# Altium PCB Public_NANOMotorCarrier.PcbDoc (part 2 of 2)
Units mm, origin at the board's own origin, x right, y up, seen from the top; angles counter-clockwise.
Board outline 50 x 80 mm, 4 copper layers (Top, PWR, GND, Bottom), stack 1.612 mm thick; 200 components, 139 nets, 723 pads, 320 vias.
Unrouted connection lines stored in the file: 53.
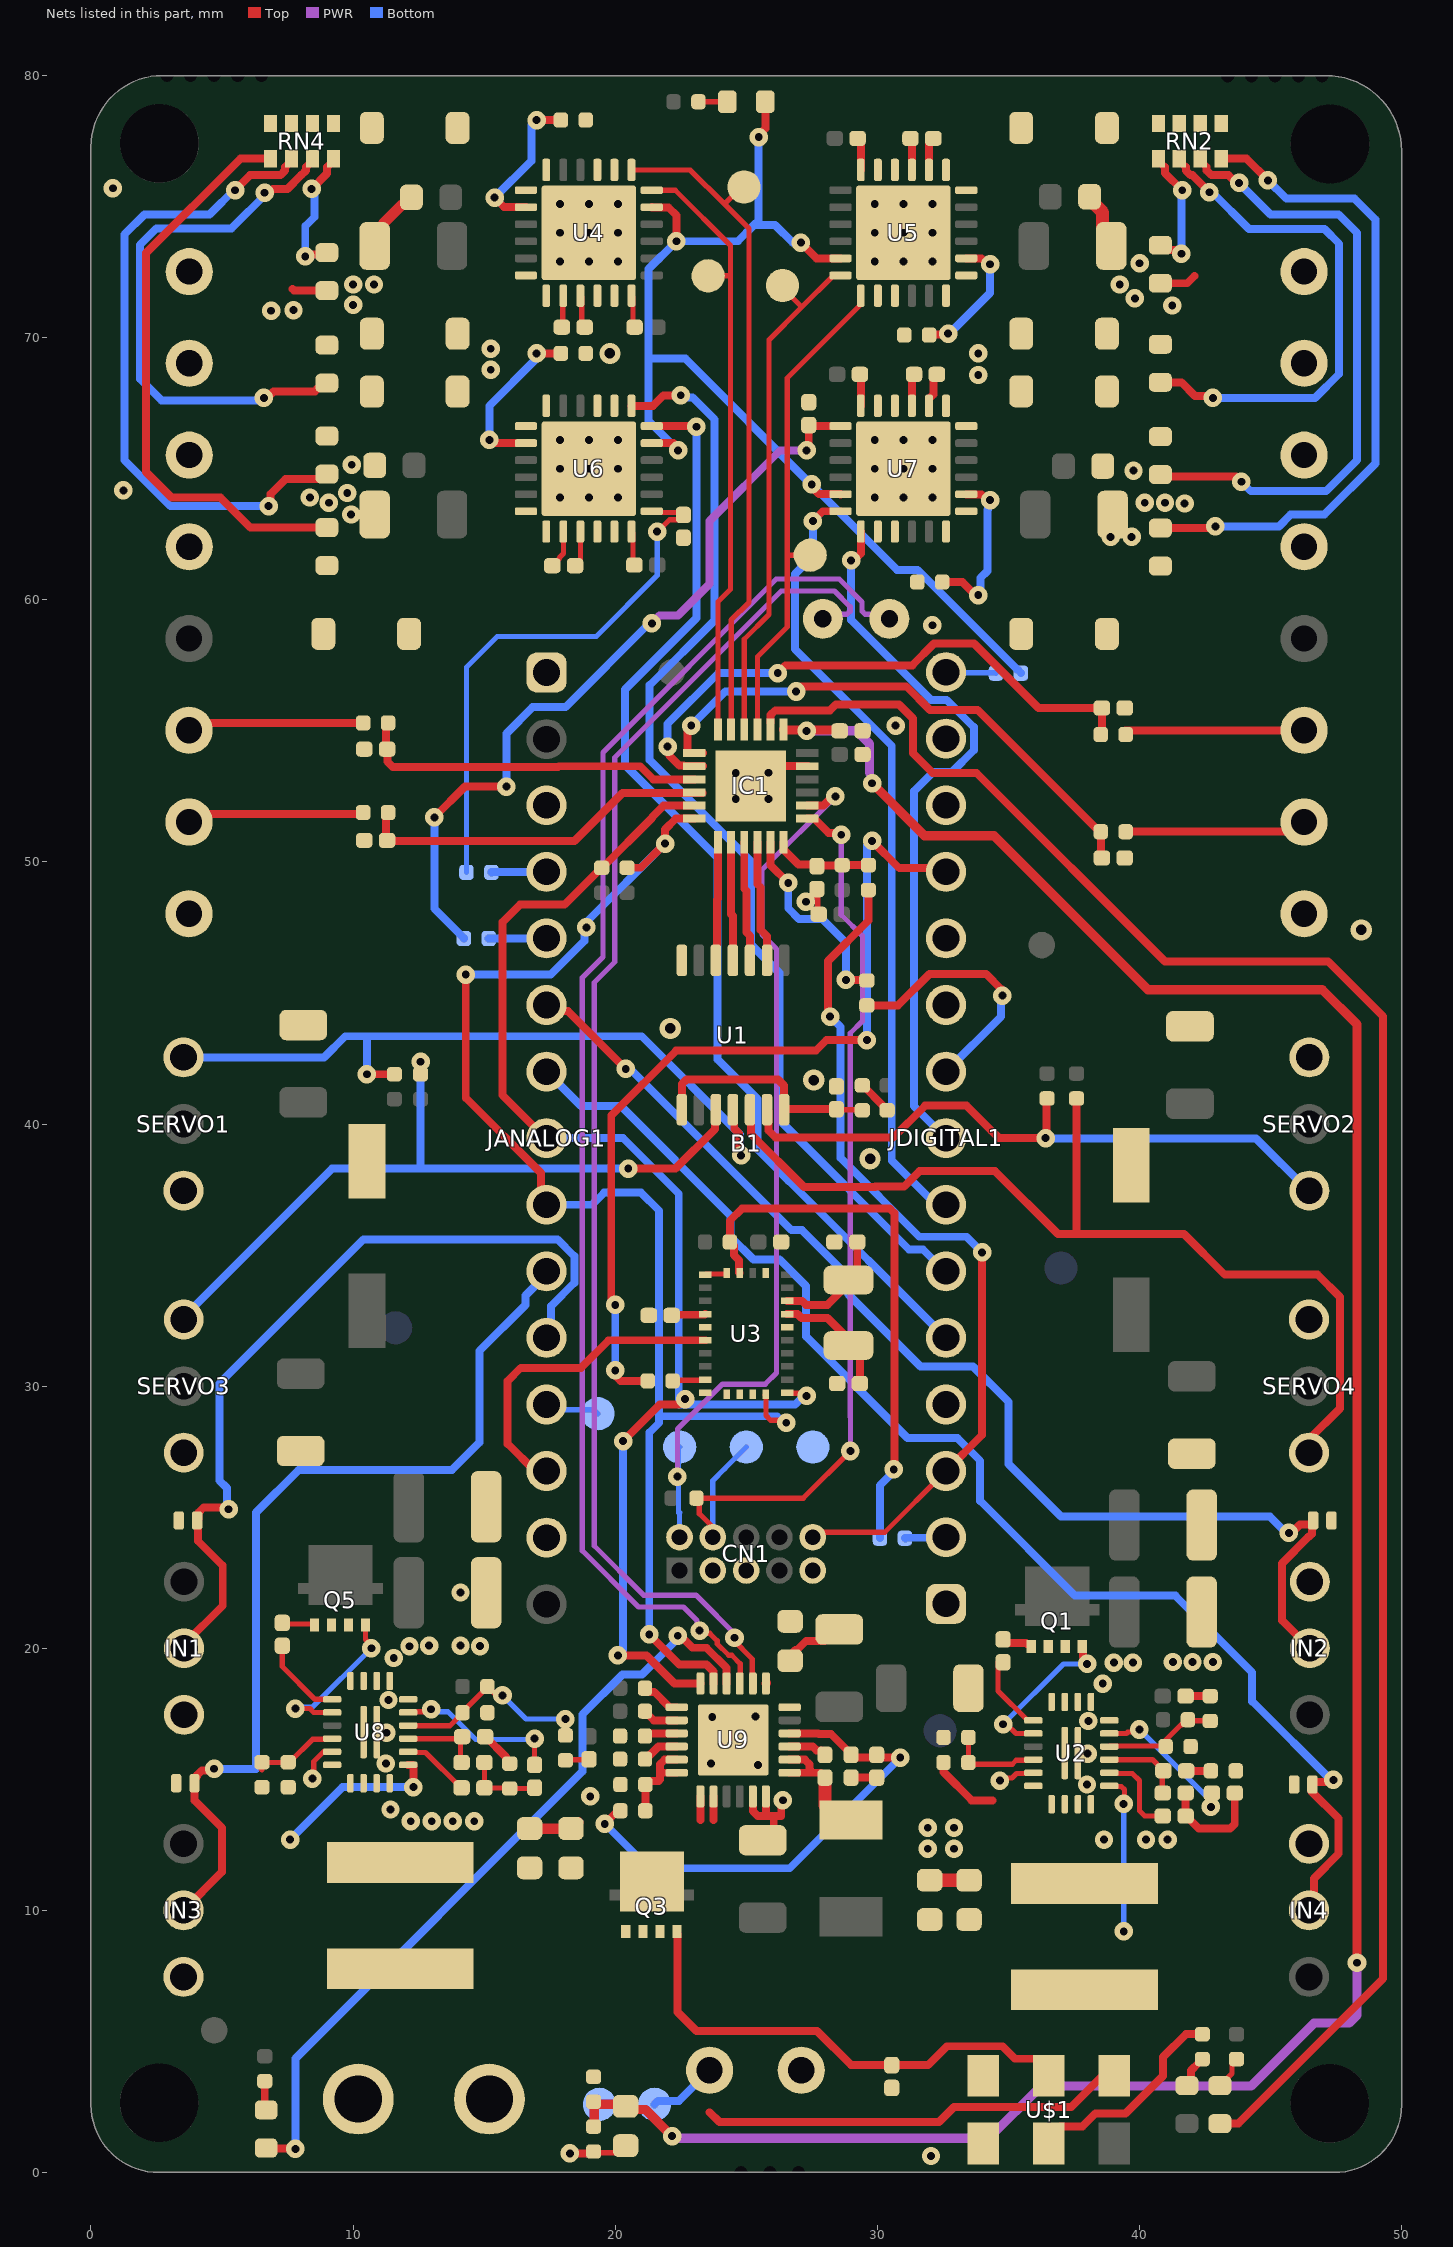
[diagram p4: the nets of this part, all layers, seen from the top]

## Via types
v1: diameter 0.706, hole 0.3, Top to Bottom, tented both sides, 206 vias
v2: diameter 0.7, hole 0.3, Top to Bottom, tented both sides, 86 vias
v3: diameter 0.706/0.706/0.706/0.706 (per signal layer), hole 0.3, Top to Bottom, tented both sides, 17 vias
v4: diameter 0.806/0.806/0.806/0.806 (per signal layer), hole 0.4, Top to Bottom, tented both sides, 5 vias
v5: diameter 0.706, hole 0.3, Top to Bottom, 4 vias
v6: diameter 0.7, hole 0.3, Top to Bottom, 1 vias
v7: diameter 0.706, hole 0.3, Top to Bottom, tented bottom, 1 vias

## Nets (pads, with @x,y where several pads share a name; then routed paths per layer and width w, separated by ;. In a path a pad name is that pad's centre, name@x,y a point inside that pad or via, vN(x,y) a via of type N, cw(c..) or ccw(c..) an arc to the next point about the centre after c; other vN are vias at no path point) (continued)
/SF: DL9.C R3.2 U4.23 U5.23 U6.23 U7.23 | length 44.7
  Top w0.305: U6.23@21.4,65.975 21.402,65.973 22.221,65.973 22.4,65.794 v1(22.4,65.7) ; U4.23@21.4,74.975 21.402,74.973 22.027,74.973 22.334,74.666 v1(22.334,73.677) ; v7(25.475,77.65) 25.475,77.725 25.725,77.975 DL9.C@25.725,79 ; v1(27.082,73.628) 27.685,73.025 U5.23@28.6,73.025 ; v1(27.5,64.4) 27.4,64.4 27.773,64.027 28.598,64.027 U7.23@28.6,64.025
  Bottom w0.305: v1(22.4,65.7) 21.271,66.828 21.271,69.2 ; v7(25.475,77.65) 25.475,74.475 25.3,74.3 ; v1(27.082,73.628) 26.772,73.628 26.1,74.3 25.3,74.3 ; R3.2@35.475,57.2 35.475,57.215 35.352,57.338 35.337,57.338 31.531,61.144 30.756,61.144 v1(27.5,64.4) 27.475,64.4 22.675,69.2 21.271,69.2 ; 21.271,69.2 21.271,72.615 v1(22.334,73.677) 24.677,73.677 25.3,74.3
A2: B1.6 D1.2 IN2.2 JANALOG1.6 | length 45.3
  Top w0.305: JANALOG1.6@17.38,44.54 17.613,44.307 18.193,44.307 v1(20.4,42.1) ; v5(45.7,24.4) 45.809,24.4 46.126,24.718 D1.2@46.577,24.718 ; IN2.2@46.5,20 45.436,21.064 45.436,23.236 46.435,24.235 46.446,24.235 46.577,24.366 D1.2@46.577,24.718 ; D1.2@46.625,24.875 46.577,24.827 D1.2@46.577,24.718
  Bottom w0.305: v1(20.4,42.1) 20.573,42.1 26.723,35.95 27.125,35.95 28.9,34.175 28.9,33.5 31.652,30.748 33.652,30.748 35,29.4 35,27.034 37.009,25.025 44.975,25.025 45.6,24.4 v5(45.7,24.4)
A3: B1.7 D2.2 IN4.2 JANALOG1.7 | length 51
  Top w0.3: D2.2@46.55,14.85 46.597,14.897 47.322,14.897 v1(47.4,14.975)
  Top w0.305: IN4.2@46.47,10 46.655,10.184 46.655,11.219 47.6,12.165 47.6,13.5 46.55,14.55 D2.2@46.55,14.85
  Bottom w0.305: JANALOG1.7@17.38,42 18.697,40.683 20.217,40.683 24.4,36.5 24.4,35.7 25.275,34.825 26.275,34.825 27.275,33.825 27.275,31.9 31.15,28.025 33.05,28.025 33.925,27.15 33.925,25.625 37.544,22.006 41.369,22.006 44.3,19.075 44.3,17.975 v1@47.4,14.875
A6: B1.10 D4.2 IN3.2 JANALOG1.10 | length 35.6
  Top w0.305: IN3.2@3.53,10 5,11.47 5,13.15 3.95,14.2 D4.2@3.95,14.85 3.95,15 4.05,15.1 4.05,15.156 4.229,15.335 4.635,15.335 v1(4.7,15.4)
  Bottom w0.305: v1(4.7,15.4) 6.3,15.4 6.3,25.175 7.925,26.8 13.766,26.8 14.817,27.85 14.817,31.342 16.575,33.1 16.575,33.461 17.38,34.266 JANALOG1.10@17.38,34.38
A7: B1.11 D3.2 IN1.2 JANALOG1.11 | length 31.9
  Top w0.3: IN1.2@3.55,20 3.55,20.15 5.025,21.625 5.025,23.15 4.09,24.085 D3.2@4.09,24.6 ; D3.2@4.05,24.875 4.1,24.925 4.1,25.174 4.301,25.375 5.175,25.375 v5(5.25,25.3)
  Bottom w0.3: v5@5.175,25.35 v5@5.175,25.454 ; JANALOG1.11@17.38,31.84 17.554,32.014 17.554,33.052 18.442,33.94 18.442,34.958 17.8,35.6
  Bottom w0.305: v5(5.25,25.3) 5.188,25.362 5.188,26.11 4.898,26.4 4.898,30.098 10.4,35.6 17.8,35.6
AREF: B1.3 JANALOG1.3
BATT+1: BATT+1.X J6.+ Q3.1 Q3.2 Q3.3 R15.2 TB5.1 U$1.6 | length 19
  Top w0.3: 23.6,2.3 23.975,1.925 32.35,1.925 32.925,2.5 37.4,2.5 38.59,3.69 U$1.6@39.039,3.69
  Bottom w0.3: BATT+1.X@21.5,2.6 21.634,2.734 22.434,2.734 TB5.1@23.6,3.9
BNO055_NBOOT: R9.2 R14.2 U3.4 | length 21.3
  Top w0.3: R14.2@24.375,35.5 24.375,36.306 24.844,36.775 30.474,36.775 30.65,36.599 30.65,26.85 v1(30.625,26.825) ; R14.2@24.382,35.5 24.525,35.357 24.525,35 24.725,34.8 24.725,34.337 U3.4@24.75,34.312
  Bottom w0.3: R9.2@30.1,24.2 30.1,26.214 30.625,26.739 v1(30.625,26.825)
BST: C28.2 U8.1 | length 3.2
  Top w0.2: C28.2@7.3,20.095 7.3,19.3 8.55,18.05 U8.1@9.2,18.05
BST2: C46.2 U2.1 | length 2.9
  Top w0.2: C46.2@34.6,19.465 34.6,18.375 35.725,17.25 U2.1@35.95,17.25
CAP_bno: C7.2 U3.9 | length 1.3
  Top w0.3: C7.2@22.152,32.7 22.177,32.725 23.412,32.725 U3.9@23.437,32.75
CE_bq: R44.2 U9.9 | length 1.3
  Top w0.3: R44.2@21.135,16.65 21.235,16.75 U9.9@22.345,16.75
COMP: C21.2 C45.1 U8.13 | length 2.9
  Top w0.2: U8.13@12.1,16.55 12.105,16.545 C21.2@14.1,16.545 ; C21.2@14.1,16.54 14.1,15.664 14.124,15.64 C45.1@14.14,15.64
COMP2: C56.1 C57.2 U2.13 | length 3.1
  Top w0.2: U2.13@38.85,15.75 40.493,15.75 40.843,15.4 40.85,15.4 40.87,15.38 40.87,14.495 C56.1@40.89,14.475
D6~: B1.24 JDIGITAL1.9 R13.1 | length 10.3
  Top w0.3: R13.1@29.6,44.525 30.791,44.525 31.991,45.725 34.15,45.725 34.75,45.125 34.75,44.925 v1(34.775,44.9) ; JDIGITAL1.9@32.366,42.234 JDIGITAL1.9@32.6,42
  Bottom w0.3: JDIGITAL1.9@32.62,42 34.717,44.097 34.717,44.842 v1(34.775,44.9)
D7: B1.25 JDIGITAL1.10 | length 0
  Bottom w0.3: JDIGITAL1.10@32.6,44.54 JDIGITAL1.10@32.62,44.52
D8: B1.26 JDIGITAL1.11 | length 0
  Bottom w0.305: JDIGITAL1.11@32.6,47.08 JDIGITAL1.11@32.61,47.09
D9~: B1.27 JDIGITAL1.12 R12.2 | length 33.6
  Top w0.3: v1(20,30.6) 19.8,30.6 20.2,30.2 R12.2@21.242,30.2 ; v1(20,33.1) 19.847,33.253 19.847,40.323 22.324,42.8 27.655,42.8 28.055,43.2 v1(29.6,43.2) ; v1(29.8,50.8) 30.84,49.76 32.48,49.76 32.48,49.62 JDIGITAL1.12@32.62,49.62
  Bottom w0.3: v1(20,30.6) v1(20,33.1) ; v1(29.6,43.2) 29.6,50.624 29.776,50.8 v1(29.8,50.8)
EN_MP34: R18.1 R34.2 U8.4 | length 3.4
  Top w0.2: 6.525,15.35 6.488,15.387 6.488,15.65 R34.2@6.525,15.65 ; R34.2@6.575,15.637 7.562,15.637 7.6,15.675 8.45,16.525 9.175,16.525 U8.4@9.2,16.55
EN_MP34_2: R17.1 R21.2 U2.4 | length 3.5
  Top w0.2: R21.2@33.475,16.6 R17.1@33.475,15.64 33.54,15.575 35.15,15.575 35.3,15.725 35.925,15.725 U2.4@35.95,15.75
FB: R22.1 R36.1 R37.2 U8.14 | length 7.8
  Top w0.2: U8.14@12.1,17.05 12.106,17.044 13.694,17.044 14.175,17.525 R37.2@14.175,17.54 14.175,17.565 15.125,18.515 R22.1@15.125,18.54 15.465,18.2 v1(15.7,18.2) ; R36.1@18.1,16.675 v1(18.1,17.3)
  Bottom w0.2: v1(15.7,18.2) 16.6,17.3 v1(18.1,17.3)
FB2: R27.2 R32.1 R33.1 U2.14 | length 4.3
  Top w0.2: U2.14@38.85,16.25 38.869,16.269 40.794,16.269 40.794,16.284 41.595,17.085 41.635,17.085 41.8,17.25 41.812,17.238 42.687,17.238 R32.1@42.7,17.225
FB_M3: C62.2 R1.1 U6.19 | length 20.7
  Top w0.2: U6.19@21.4,63.375 21.45,63.325 22.51,63.325 C62.2@22.6,63.235 22.416,63.051 22.076,63.051 21.625,62.6 v1(21.6,62.6)
  Bottom w0.2: R1.1@14.325,49.6 14.325,57.425 15.5,58.6 19.275,58.6 21.6,60.925 v1(21.6,62.6)
FB_M4: C61.2 R8.1 U7.19 | length 29.9
  Top w0.305: v1(13.1,51.7) 14.275,52.875 v1(15.85,52.875) ; v1(27.3,65.7) 27.384,65.784 C61.2@27.384,66.665 27.421,66.627 28.598,66.627 U7.19@28.6,66.625
  PWR w0.305: v1(21.4,59.1) 21.694,59.394 22.397,59.394 23.6,60.598 23.6,63 26.3,65.7 v1(27.3,65.7)
  Bottom w0.305: v1(13.1,51.7) 13.1,48.22 14.225,47.095 R8.1@14.225,47.08 R8.1@14.215,47.09 ; v1(15.85,52.875) 15.85,54.9 16.85,55.9 18.1,55.9 21.3,59.1 v1(21.4,59.1)
GND: B1.14 B1.19 C1.1 C2.1 C3.1 C4.1 C5.1 C6.1 C7.1 C10.1 C11.1 C12.1 C13.1 C14.1 C15.2 C16.1 C17.2 C18.1 C19.1 C20.1 C22.2 C23.1 C24.1 C25.1 C26.1 C27.1 C29.1 C31.1 C38.1 C39.1 C40.1 C41.1 C42.1 C43.1 C44.1 C45.2 C48.2 C49.1 C50.1 C51.1 C52.1 C53.1 C55.1 C56.2 C58.1 C59.1 C60.1 C61.1 C62.1 C63.2 C64.1 C65.2 CBUS.2 CN1.3 CN1.5 CN1.9 D1.1 D2.1 D3.1 D4.1 D5.A D6.A D7.A D8.A D9.A D10.A D11.A D12.A IC1.23 IC1.EXP IN1.3 IN2.3 IN3.3 IN4.3 J6.- JANALOG1.14 JDIGITAL1.4 R21.1 R23.1 R27.1 R28.1 R29.1 R30.1 R31.1 R34.1 R35.1 R37.1 R38.1 R41.2 R44.1 R45.1 RN2.1 RN2.2 RN2.3 RN2.4 RN4.1 RN4.2 RN4.3 RN4.4 SERVO1.3 SERVO2.3 SERVO3.3 SERVO4.3 TB5.2 TP2.X TP-GND.X U1.7 U2.5 U2.9 U2.10 U2.16 U2.17 U2.18 U2.22 U3.2 U3.5 U3.6 U3.10 U3.15 U3.16 U3.17 U3.18 U3.25 U4.2 U4.3 U4.16 U4.17 U4.25 U5.2 U5.3 U5.16 U5.17 U5.25 U6.2 U6.3 U6.16 U6.17 U6.25 U7.2 U7.3 U7.16 U7.17 U7.25 U8.5 U8.9 U8.10 U8.16 U8.17 U8.18 U8.22 U9.17 U9.18 U9.EXP U$1.1 U$1.4 X2A.1 X3B.2 | length 34.8
  Top w0.2: v1(8.45,15.025) 8.5,15.075 8.5,15.678 8.871,16.05 U8.5@9.2,16.05 ; C45.2@15.01,15.64 C29.1@15.01,14.677 15.023,14.663 15.962,14.663 R35.1@15.975,14.65 ; R35.1@15.975,14.63 15.995,14.65 C44.1@16.875,14.65 ; R38.1@19.175,0.75 20.009,0.75 20.024,0.765 C63.2@20.7,0.765 ; U3.6@23.437,34.25 23.462,34.275 24.225,34.275 24.25,34.3 U3.5@24.25,34.312 ; v1(27.276,48.477) 27.381,48.477 C22.2@27.854,48.95 ; C22.2@27.729,48.929 27.729,48.036 C20.1@27.765,48 ; v1(34.677,14.951) 34.776,15.05 35.137,15.05 35.312,15.225 35.925,15.225 U2.5@35.95,15.25
  Top w0.3: v1(18.275,0.725) 19.175,0.725 R38.1@19.2,0.75 ; U9.17@25.25,14.345 25.25,13.788 25.426,13.612 ; U9.18@25.75,14.345 25.75,13.612 25.426,13.612 ; C52.1@26.05,12.8 26.05,13.6 ; v1(26.4,14.2) 26.335,14.135 26.335,13.6 26.05,13.6 ; CBUS.2@26.735,19.8 26.875,19.94 26.944,19.94 27.286,20.281 27.981,20.281 C50.1@28.35,20.65 ; C48.2@29,15.065 C65.2@29.975,15.065 ; C56.2@41.76,14.475 C53.1@41.76,13.6 41.785,13.6 42.264,13.121 43.459,13.121 43.635,13.296 C55.1@43.635,14.475 ; 25.426,13.612 25.438,13.6 26.05,13.6
  Top w0.305: IC1.EXP@24.949,53.709 25.051,53.501 25.349,52.899 25.649,52.899 25.996,53.246 26.399,53.649 IC1.23@27.349,53.649
  Top w0.4: C2.1@10.825,73 11.175,73.35 11.175,74.374 11.878,75.078 11.992,75.078 12.225,75.312 C10.1@12.225,75.35 ; C11.1@16.737,13.121 C18.1@18.313,13.121 18.351,13.121 C18.1@18.584,13.354
  Top w0.5: C4.1@32,11.15 C6.1@33.5,11.15 ; C59.1@38.05,75.375 38.05,75.325 38.595,74.78 38.595,73.83 C3.1@38.925,73.5
  Bottom w0.2: v1(27.276,48.477) 27.377,48.477 27.85,48.95
  other v1: 25.45,15.55 23.65,15.6 25.35,17.4 24.599,52.399 25.844,52.399 24.599,53.389 25.844,53.399 30.7,55.2 17.9,63.9 19,63.9 20.1,63.9 29.9,63.9 31,63.9 32.1,63.9 17.9,65 19,65 20.1,65 29.9,65 31,65 32.1,65 17.9,66.1 19,66.1 20.1,66.1 29.9,66.1 31,66.1 32.1,66.1 17.9,72.9 19,72.9 20.1,72.9 29.9,72.9 31,72.9 32.1,72.9 17.9,74 19,74 20.1,74 29.9,74 31,74 32.1,74 17.9,75.1 19,75.1 20.1,75.1 29.9,75.1 31,75.1 32.1,75.1
  other v2: 31.925,12.35 32.925,12.35 38.65,12.7 40.25,12.7 41.075,12.7 31.925,13.15 32.925,13.15 12.2,13.4 13,13.4 13.8,13.4 14.625,13.4 11.425,13.85 19.05,14.35 38,14.8 11.25,15.6 38.023,15.978 11.273,16.775 38.05,17.225 23.7,17.375 11.35,18.025 38.6,18.65 39.025,19.45 39.75,19.45 41.275,19.475 42.025,19.475 42.8,19.475 11.55,19.625 12.15,20.075 12.9,20.1 14.1,20.1 14.841,20.08 14.1,22.125 32.1,59.025 38.9,62.4 39.7,62.4 9.925,63.25 41.725,63.675 9.075,63.7 40.2,63.7 40.975,63.7 8.35,63.9 9.775,64.075 39.775,64.925 9.95,65.15 33.85,68.575 15.25,68.775 33.85,69.4 15.25,69.575 6.875,71.025 7.725,71.05 41.25,71.225 10,71.25 39.825,71.5 10,72.025 10.8,72.025 39.25,72.025 40.009,72.839
  other v3: 1.24,64.17 0.835,75.7
  other v4: 29.725,38.675 27.575,41.675 22.1,43.65 48.46,47.405 19.8,69.4
  other v6: 32.05,0.63
HA_E1: C17.1 IC1.9 R7.1 | length 13.5
  Top w0.3: R7.1@11.275,55.3 11.255,55.28 11.255,54.32 11.235,54.3 11.313,54.223 11.313,53.825 11.514,53.623 17.82,53.623 17.846,53.649 20.951,53.649 21.451,53.149 IC1.9@23.019,53.149
HA_E2: C14.2 IC1.8 R4.1 | length 22.6
  Top w0.305: v3(22,54.4) 22.077,54.323 22.077,54.049 22.457,53.669 22.6,53.669 22.617,53.651 23.016,53.651 IC1.8@23.019,53.649 IC1.8@23.349,53.649 ; v1(26.2,57.2) 26.5,57.5 31.335,57.5 32.168,58.332 33.693,58.332 36.15,55.875 38.565,55.875 C14.2@38.565,55.87 38.565,54.86 R4.1@38.525,54.86
  Bottom w0.305: v3(22,54.4) 22,55.266 23.934,57.2 v1(26.2,57.2)
HB_E1: C16.2 IC1.10 R6.1 | length 14
  Top w0.3: C16.2@11.225,50.82 11.245,50.8 18.45,50.8 20.069,52.419
  Top w0.305: C16.2@11.225,50.82 11.25,50.845 11.25,51.855 R6.1@11.275,51.88 ; 20.069,52.419 20.279,52.629 IC1.10@23.329,52.629
HB_E2: C15.1 IC1.7 R5.1 | length 21.1
  Top w0.305: v3(22.9,55.2) 22.749,55.049 22.749,54.202 22.802,54.149 IC1.7@23.019,54.149 IC1.7@23.349,54.149 ; v1(26.9,56.5) 27.1,56.7 31.1,56.7 32.008,55.792 33.828,55.792 R5.1@38.387,51.233 ; R5.1@38.525,51.15 38.525,50.15 C15.1@38.565,50.15
  Bottom w0.305: v3(22.9,55.2) 24.2,56.5 v1(26.9,56.5)
ILIM_bq: R41.1 U9.10 | length 1.4
  Top w0.3: R41.1@21.135,15.77 21.135,15.785 21.26,15.91 21.31,15.91 21.65,16.25 U9.10@22.345,16.25
IN1_M1: IC1.5 TP6.X U4.1 | length 25.8
  Top w0.2: U4.1@20.625,76.4 22.859,76.4 24.166,75.093 ; IC1.5@24.424,55.054 24.424,59.224 25.1,59.9 25.1,74.159 24.166,75.093 ; TP6.X@24.917,75.749 24.822,75.749 24.166,75.093
IN1_M2: IC1.3 TP8.X U5.1 | length 19.1
  Top w0.2: IC1.3@25.446,55.076 IC1.3@25.424,55.054 25.424,57.824 26.563,58.963 26.563,61.7 ; TP8.X@27.44,61.7 26.563,61.7 ; U5.1@29.375,71.6 29.375,71.275 26.563,68.463 26.563,61.7
IN1_M3: B1.21 JDIGITAL1.6 U6.1 | length 42.2
  Top w0.305: U6.1@20.625,67.4 21.446,67.4 21.846,67.8 v1(22.5,67.8)
  Bottom w0.305: v1(22.5,67.8) 22.577,67.723 22.943,67.723 23.783,66.883 23.783,59.208 21.317,56.742 21.317,53.883 25.178,50.022 25.178,46.847 26.265,45.76 26.265,40.156 31.201,35.22 31.736,35.22 32.575,34.38 JDIGITAL1.6@32.62,34.38
IN1_M4: B1.23 JDIGITAL1.8 U7.1 | length 27.5
  Top w0.305: v1(29,61.5) 29.1,61.5 29.373,61.773 29.373,62.598 U7.1@29.375,62.6
  Bottom w0.3: v1(29,61.5) 29,59.231 32.053,56.178 32.644,56.178 33.682,55.14 33.682,54.26 32.852,53.43 32.13,53.43 31.4,52.7 31.4,40.68 JDIGITAL1.8@32.62,39.46
IN2_M1: IC1.6 TP7.X U4.24 | length 23.4
  Top w0.2: U4.24@21.4,75.625 22.29,75.625 24.4,73.515 24.4,72.323 ; TP7.X@23.547,72.358 24.365,72.358 24.4,72.323 ; IC1.6@23.944,55.073 IC1.6@23.924,55.054 23.924,59.924 24.4,60.4 24.4,72.323
IN2_M2: IC1.4 TP9.X U5.24 | length 20.1
  Top w0.2: IC1.4@24.924,55.054 24.924,58.495 25.865,59.436 25.865,69.915 27.115,71.165 ; TP9.X@26.384,71.989 26.384,71.897 27.115,71.165 ; U5.24@28.6,72.375 28.325,72.375 27.115,71.165
IN2_M3: B1.20 JDIGITAL1.5 U6.24 | length 42.7
  Top w0.305: U6.24@21.4,66.625 21.402,66.623 23.077,66.623 v1(23.1,66.6)
  Bottom w0.305: v1(23.1,66.6) 23.1,59.3 20.375,56.575 20.375,53.691 23.908,50.159 23.908,42.467 25.425,40.95 25.425,39.035 26.217,38.243 26.217,38.217 26.617,37.817 26.643,37.817 JDIGITAL1.5@32.62,31.84
IN2_M4: B1.22 JDIGITAL1.7 U7.24 | length 30.4
  Top w0.3: v1(27.54,63) 27.546,63 27.921,63.375 U7.24@28.6,63.375
  Bottom w0.3: v1@27.54,63.2 v1(27.54,63) 27.54,61.66 26.859,60.979 26.859,58.117 30.55,54.426 30.55,38.605 32.235,36.92 JDIGITAL1.7@32.62,36.92
INT_bq: R43.2 U9.7 | length 1.5
  Top w0.3: R43.2@21.135,18.475 21.135,18.46 21.26,18.335 21.485,18.335 22.07,17.75 U9.7@22.345,17.75
LED_S: DL10.C IC1.2 | length 74.7
  Top w0.305: IC1.2@25.926,55.326 25.926,55.598 26.109,55.781 28.195,55.781 28.414,56 30.827,56 31.356,55.472 31.356,54.144 32.1,53.4 33.775,53.4 40.975,46.2 47.2,46.2 49.3,44.1 49.3,7.395 43.77,1.865 DL10.C@43.07,1.865
M1+: D6.C DL1.A U4.6 U4.7 X6A.1 | length 1.3
  Top w0.3: 7.683,71.862 7.75,71.795 DL1.A@9,71.795
M1-: D5.C DL2.A U4.12 U4.13 X6A.2
M2+: D7.C DL8.A U5.12 U5.13 X1B.2 | length 1.4
  Top w0.3: DL8.A@40.8,72.075 41.822,72.075 42.105,72.358
M2-: D8.C DL7.A U5.6 U5.7 X1B.1
M3+: D12.C DL3.A U6.6 U6.7 X6B.1
M3-: D11.C DL4.A U6.12 U6.13 X6B.2
M4+: D9.C DL6.A U7.12 U7.13 X1A.2
M4-: D10.C DL5.A U7.6 U7.7 X1A.1
NetB1_4: B1.4 JANALOG1.4 R1.2 | length 2.1
  Bottom w0.305: R1.2@15.275,49.6 15.285,49.61 17.37,49.61 JANALOG1.4@17.38,49.62
NetB1_5: B1.5 JANALOG1.5 R8.2 | length 2.2
  Bottom w0.305: R8.2@15.175,47.08 JANALOG1.5@17.38,47.08
NetB1_28: B1.28 JDIGITAL1.13
NetB1_29: B1.29 JDIGITAL1.14
NetB1_30: B1.30 JDIGITAL1.15 R3.1 | length 1.9
  Bottom w0.2: JDIGITAL1.15@32.62,57.24 32.64,57.22 34.505,57.22 R3.1@34.525,57.2
NetC9_1: C9.1 U5.18 | length 1.3
  Top w0.305: C9.1@29.245,77.6 29.373,77.473 29.373,76.402 U5.18@29.375,76.4
NetC19_2: C19.2 R10.1 U1.8 U1.14 | length 9
  Top w0.2: C19.2@28.439,40.564 28.459,40.544 29.409,40.544 R10.1@29.429,40.524
  Top w0.305: U1.8@22.542,40.545 22.542,41.521 22.72,41.7 26.215,41.7 26.442,41.474 U1.14@26.442,40.545 26.46,40.564 C19.2@28.439,40.564
NetC21_1: C21.1 R35.2 | length 1.4
  Top w0.305: C21.1@15.035,16.625 15.06,16.625 15.837,15.848 15.837,15.723 15.96,15.6 R35.2@15.975,15.6
NetC29_2: C29.2 U8.12 | length 2.6
  Top w0.2: U8.12@12.1,16.05 12.125,16.025 12.767,16.025 14.115,14.677 C29.2@14.14,14.677
NetC30_2: C30.2 R36.2 | length 0.9
  Top w0.2: R36.2@18.1,15.725 18.12,15.745 18.98,15.745 C30.2@19,15.765
NetC32_1: C32.1 U4.14 | length 1.2
  Top w0.2: C32.1@17.965,70.4 17.995,70.43 17.995,71.57 U4.14@18.025,71.6
NetC32_2: C32.2 U4.15 | length 1.3
  Top w0.2: U4.15@18.675,71.6 18.725,71.55 18.725,70.51 C32.2@18.835,70.4
NetC33_1: C33.1 U5.14 | length 1.3
  Top w0.3: U5.14@31.975,76.4 31.975,77.46 32.115,77.6 C33.1@32.135,77.6
NetC33_2: C33.2 U5.15 | length 1.2
  Top w0.305: C33.2@31.265,77.6 31.323,77.542 31.323,76.402 U5.15@31.325,76.4
NetC34_1: C34.1 U7.18 | length 1.2
  Top w0.305: C34.1@29.335,68.6 29.373,68.562 29.373,67.402 U7.18@29.375,67.4
NetC35_1: C35.1 U6.18 | length 1.3
  Top w0.2: U6.18@20.625,62.6 20.675,62.55 20.675,61.38 C35.1@20.73,61.325
NetC36_1: C36.1 U7.14 | length 1.3
  Top w0.305: U7.14@31.975,67.4 31.975,67.67 32.145,67.84 32.145,68.475 C36.1@32.27,68.6
NetC36_2: C36.2 U7.15 | length 1.2
  Top w0.305: U7.15@31.325,67.4 31.327,67.402 31.327,68.527 C36.2@31.4,68.6
NetC37_1: C37.1 U6.14 | length 1.5
  Top w0.2: C37.1@17.6,61.3 17.6,61.302 17.877,61.58 17.877,61.617 18.025,61.765 U6.14@18.025,62.6
NetC37_2: C37.2 U6.15 | length 1.4
  Top w0.2: C37.2@18.47,61.3 18.675,61.505 U6.15@18.675,62.6
NetC42_2: C42.2 U3.27 XTAL-32768Hz.2 | length 4.5
  Top w0.3: U3.27@26.563,33.25 27.132,33.25 27.282,33.1 28.1,33.1 28.75,33.75 28.75,33.9 29.235,34.385 C42.2@29.235,35.5
NetC43_2: C43.2 U3.26 XTAL-32768Hz.1 | length 4.6
  Top w0.3: XTAL-32768Hz.1@28.9,31.55 28.944,31.55 29.335,31.16 C43.2@29.335,30.1
  Top w0.305: U3.26@26.563,32.75 26.952,32.75 27.103,32.6 28.1,32.6 28.748,31.952 28.748,31.702 XTAL-32768Hz.1@28.9,31.55
NetC44_2: C44.2 U8.15 | length 6.3
  Top w0.2: U8.15@12.1,17.55 12.125,17.575 12.738,17.575 12.838,17.675 v1(12.975,17.675) ; C44.2@16.925,15.55 v1(16.925,16.55)
  Bottom w0.2: v1(12.975,17.675) 13.072,17.578 13.622,17.578 14.68,16.52 v1@16.875,16.52
NetC47_1: C47.1 U9.21 | length 1.5
  Top w0.3: U9.21@26.655,16.25 27.535,16.25 27.685,16.1 27.86,16.1 28,15.96 C47.1@28,15.935
NetC51_2: C51.2 Q3.4 U$1.5 | length 19
  Top w0.3: Q3.4@22.355,9.19 22.355,9.125 22.38,9.1 22.38,6.12 23.1,5.4 27.7,5.4 29,4.1 30.55,4.1 31.94,4.1 32.658,4.818 34.774,4.818 35.252,4.34 36.089,4.34 36.539,3.89 U$1.5@36.539,3.69
NetC53_2: C53.2 U2.12 | length 3.4
  Top w0.2: U2.12@38.85,15.25 38.875,15.225 39.725,15.225 40,14.95 40,13.8 40.2,13.6 C53.2@40.89,13.6
NetC54_2: C54.2 R32.2 | length 0.9
  Top w0.305: C54.2@41.76,18.175 R32.2@42.7,18.175
NetC55_2: C55.2 U2.15 | length 5.9
  Top w0.2: U2.15@38.85,16.75 39.5,16.75 39.553,16.803 39.903,16.803 v1(40,16.9) ; v1(42.725,13.95) 42.725,14.285 42.65,14.36 C55.2@42.765,14.475
  Bottom w0.2: v1(40,16.9) 42.725,14.175 v1(42.725,13.95)
NetC57_1: C57.1 R23.2 | length 0.9
  Top w0.305: C57.1@41.785,15.325 R23.2@42.725,15.325
NetDL1_C: DL1.C RN4.8 | length 5.1
  Top w0.305: v1(8.175,73.1) 8.247,73.172 8.928,73.172 DL1.C@9,73.245 ; v1(8.42,75.674) 9.003,76.257 9.003,76.503 9.25,76.75 RN4.8@9.25,76.825
  Bottom w0.305: v1(8.175,73.1) 8.175,74.252 8.52,74.597 v1@8.52,75.674
NetDL2_C: DL2.C RN4.7 | length 21
  Top w0.305: v3(6.6,67.7) 6.709,67.7 6.959,67.95 8.539,67.95 8.663,68.074 8.809,68.074 DL2.C@9,68.265 ; v3(6.625,75.529) 6.797,75.529 6.943,75.675 7.493,75.675 8.016,76.198 8.025,76.198 8.202,76.375 8.202,76.503 8.45,76.75 RN4.7@8.45,76.825
  Bottom w0.305: v3(6.6,67.7) 6.5,67.6 2.7,67.6 1.87,68.43 1.87,73.54 2.5,74.17 5.367,74.17 v3@6.725,75.529
NetDL3_C: DL3.C RN4.6 | length 25.5
  Top w0.305: v3(5.5,75.625) 6.073,76.198 7.225,76.198 7.403,76.375 7.403,76.503 7.65,76.75 RN4.6@7.65,76.825 ; v3(6.775,63.575) 6.852,63.652 6.852,64.027 7.43,64.605 8.809,64.605 DL3.C@9,64.795
  Bottom w0.305: v3@5.525,75.7 4.525,74.7 2.04,74.7 1.27,73.93 1.27,65.33 3.025,63.575 v3(6.775,63.575)
NetDL4_C: DL4.C RN4.5 | length 22.5
  Top w0.305: RN4.5@6.95,76.825 5.7,76.825 2.1,73.225 2.1,64.875 3.075,63.9 4.935,63.9 6.08,62.755 DL4.C@9,62.755
NetDL5_C: DL5.C RN2.8 | length 25.2
  Top w0.305: DL5.C@41.019,62.797 41.08,62.735 42.835,62.735 v3(42.9,62.8) ; RN2.8@43.12,76.825 44.084,76.825 44.9,76.009 v3(44.9,76)
  Bottom w0.305: v3(42.9,62.8) 45.32,62.8 45.77,63.25 47.053,63.25 49,65.197 49,74.5 48.2,75.3 45.609,75.3 44.909,76 v3(44.9,76)
NetDL6_C: DL6.C RN2.7 | length 24.2
  Top w0.305: DL6.C@40.8,64.775 40.8,64.7 43.69,64.7 v3(43.89,64.5) ; RN2.7@42.32,76.825 42.32,76.75 42.567,76.503 42.567,76.375 42.745,76.198 43.394,76.198 43.691,75.9 v3(43.8,75.9)
  Bottom w0.305: v3(43.8,75.9) 45,74.7 47.6,74.7 48.3,74 48.3,65.325 47.115,64.14 44.25,64.14 v3(43.89,64.5)
NetDL7_C: DL7.C RN2.6 | length 20
  Top w0.305: DL7.C@40.8,68.295 41.605,68.295 42.123,67.777 42.723,67.777 v3(42.8,67.7) ; RN2.6@41.52,76.825 41.52,76.75 41.768,76.503 41.768,76.375 41.945,76.198 42.02,76.198 v3(42.672,75.546)
  Bottom w0.305: v3(42.672,75.546) 42.779,75.546 44.185,74.14 47.06,74.14 47.62,73.58 47.62,68.62 46.7,67.7 v3(42.8,67.7)
NetDL8_C: DL8.C RN2.5 | length 4.9
  Top w0.305: RN2.5@40.72,76.825 40.72,76.75 40.967,76.503 40.967,76.285 v1(41.631,75.622) ; DL8.C@40.8,73.525 40.991,73.334 41.357,73.334 41.491,73.2 v1(41.6,73.2)
  Bottom w0.305: v1(41.6,73.2) 41.6,75.591 v1(41.631,75.622)
NetDL9_A: DL9.A R11.2 | length 1.1
  Top w0.2: R11.2@23.175,79 DL9.A@24.275,79
NetDL10_A: DL10.A R24.2 | length 1.3
  Top w0.2: DL10.A@43.07,3.315 43.102,3.315 43.356,3.569 43.356,3.601 43.535,3.78 43.535,4.16 R24.2@43.7,4.325
NetDL12_A: DL12.A R40.1 | length 1.1
  Top w0.305: DL12.A@6.6,2.4 6.63,2.43 R40.1@6.63,3.485
NetON_C: ON.C R48.1 | length 1.3
  Top w0.305: ON.C@41.775,3.308 41.964,3.497 41.964,3.889 42.262,4.187 42.262,4.202 42.385,4.325 R48.1@42.4,4.325
NetR4_2: R4.2 X2B.1 | length 7.2
  Top w0.305: R4.2@39.475,54.86 39.475,55.01 46.28,55.01 X2B.1@46.13,54.86
NetR5_2: R5.2 X2A.2 | length 7
  Top w0.305: R5.2@39.475,51.15 45.92,51.15 X2A.2@46.28,51.51
NetR6_2: R6.2 X3B.1 | length 6.8
  Top w0.305: X3B.1@3.74,51.52 4.05,51.83 7.8,51.83 7.79,51.82 10.265,51.82 R6.2@10.325,51.88
NetR7_2: R7.2 X3A.2 | length 6.7
  Top w0.305: X3A.2@3.74,55.02 4.02,55.3 R7.2@10.325,55.3
NetR10_2: R10.2 R50.1 | length 1.4
  Top w0.3: R10.2@29.429,41.474 29.444,41.474 30.235,40.682 30.235,40.65 30.36,40.525 R50.1@30.375,40.525
NetR12_1: R12.1 U3.14 | length 1.3
  Top w0.2: R12.1@22.192,30.2 22.217,30.225 23.412,30.225 U3.14@23.437,30.25
NetR28_2: R28.2 U4.8 | length 5.9
  Top w0.305: v1(15.4,75.341) 15.766,74.975 U4.8@16.6,74.975 ; v1(17,78.3) R28.2@17.925,78.3
  Bottom w0.305: v1(15.4,75.341) 16.8,76.741 16.8,78.121 16.979,78.3 v1(17,78.3)
NetR29_2: R29.2 U5.8 | length 5.1
  Top w0.305: R29.2@31.975,70.1 32.002,70.127 32.673,70.127 v1(32.7,70.153) ; U5.8@33.4,73.025 33.966,73.025 34.191,72.8 v1(34.3,72.8)
  Bottom w0.305: v1(32.7,70.153) 32.753,70.153 34.3,71.7 v1(34.3,72.8)
NetR30_2: R30.2 U6.8 | length 6.4
  Top w0.305: v1(15.2,66.1) 15.325,65.975 U6.8@16.6,65.975 ; v1(17,69.4) R30.2@17.925,69.4
  Bottom w0.305: v1(15.2,66.1) 15.2,67.4 17,69.2 v1(17,69.4)
NetR31_2: R31.2 U7.8 | length 6.4
  Top w0.305: R31.2@32.475,60.675 33.241,60.675 33.741,60.175 v1(33.85,60.175) ; U7.8@33.4,64.025 33.966,64.025 34.191,63.8 v1(34.3,63.8)
  Bottom w0.305: v1(33.85,60.175) 33.927,60.252 33.927,60.827 34.2,61.1 34.2,63.421 34.223,63.444 34.223,63.723 v1(34.3,63.8)
NetR47_2: R47.2 U9.8 | length 1.4
  Top w0.3: R47.2@21.135,17.6 21.135,17.585 21.47,17.25 U9.8@22.345,17.25
NetR48_2: R48.2 U$1.2 | length 8.1
  Top w0.305: U$1.2@36.539,1.11 36.539,1.31 36.986,1.757 37.819,1.757 38.317,2.255 39.471,2.255 40.9,3.684 40.9,4.4 41.775,5.275 R48.2@42.4,5.275
REGN: C48.1 C65.1 R16.2 U9.22 | length 19.1
  Top w0.3: v1(19.6,13.3) 20.1,13.8 R16.2@20.2,13.8 ; U9.22@26.655,16.75 27.744,16.75 27.772,16.722 28.238,16.722 29,15.96 C48.1@29,15.935 29.11,15.825 v1(30.875,15.825)
  Bottom w0.3: v1(19.6,13.3) 21.293,11.607 26.657,11.607 v1(30.875,15.825)
RESET_D11: C22.1 IC1.18 R2.1 R26.2 | length 3.8
  Top w0.305: IC1.18@26.424,50.744 26.424,50.474 26.997,49.9 27.629,49.9 C22.1@27.694,49.835 27.714,49.855 28.639,49.855 R26.2@28.659,49.875 R2.1@29.659,49.875
RST_NANO: B1.18 CN1.10 JDIGITAL1.3 R2.2 | length 32.9
  Top w0.2: CN1.10@27.535,24.425 30.285,24.425 JDIGITAL1.3@32.62,26.76
  Top w0.3: v1(28.2,44.1) 28.119,44.181 28.119,46.219 29.659,47.759 R2.2@29.659,48.925 ; JDIGITAL1.3@32.62,26.76 34,28.14 v5(34,35.1)
  Bottom w0.2: CN1.10@27.535,24.425 CN1.10@27.537,24.428
  Bottom w0.3: v1(28.2,44.1) 28.6,43.7 28.6,38.7 31.6,35.7 33.4,35.7 v5(34,35.1)
RST_NANO2: B1.13 JANALOG1.13 U3.11 | length 12.5
  Top w0.305: JANALOG1.13@17.38,26.76 16.94,26.76 15.9,27.8 15.9,30.2 16.4,30.7 18.7,30.7 19.75,31.75 U3.11@23.437,31.75
RX1: B1.17 JDIGITAL1.2 R9.1 | length 1.6
  Bottom w0.3: R9.1@31.07,24.18 R9.1@31.05,24.2 31.068,24.218 32.603,24.218 JDIGITAL1.2@32.62,24.235
SCK: B1.1 JANALOG1.1
SCL: B1.9 IC1.12 JANALOG1.9 R20.1 U3.19 U9.5 | length 55
  Top w0.2: U3.19@25.725,29.663 U3.19@25.75,29.688 25.75,28.875 25.928,28.697 26.428,28.697 v1(26.525,28.6)
  Top w0.3: v1(14.3,45.7) 14.3,40.999 17.167,38.132 17.167,37.133 JANALOG1.9@17.38,36.92 ; R20.1@20.45,49.775 20.975,49.775 v1(21.9,50.7) 21.9,51.237 22.312,51.649 IC1.12@23.019,51.649 ; v1(21.3,20.525) 22.445,19.38 23.48,19.38 23.75,19.11 U9.5@23.75,18.655
  Bottom w0.3: v1(14.3,45.7) 17.541,45.7 18.822,46.981 18.822,47.422 v1(18.9,47.5) 18.9,47.7 v1(21.9,50.7) ; JANALOG1.9@17.38,36.92 19.116,36.92 19.577,37.381 20.982,37.381 21.675,36.688 21.675,28.849 ; v1(21.3,20.525) 21.3,28.225 21.675,28.6 21.675,28.849 ; v1(26.525,28.6) 26.415,28.6 26.166,28.849 21.675,28.849
SD11_INT: IC1.17 R13.2 | length 7.8
  Top w0.3: IC1.17@25.924,50.744 25.924,49.876 v3(26.6,49.2) ; v1(28.8,45.5) 29.575,45.5 R13.2@29.6,45.475
  Bottom w0.3: v3(26.6,49.2) 26.6,48.23 27.006,47.824 27.899,47.824 28.8,46.923 v1(28.8,45.5)
SDA: B1.8 IC1.11 JANALOG1.8 R19.1 U3.20 U9.6 | length 53
  Top w0.2: U3.20@26.563,29.75 26.588,29.725 27.063,29.725 27.163,29.625 v1(27.3,29.625)
  Top w0.3: JANALOG1.8@17.38,39.46 17.34,39.46 15.7,41.1 15.7,47.7 16.368,48.368 18.063,48.368 19.475,49.78 R19.1@19.48,49.78 ; R19.1@19.485,49.775 R19.1@19.48,49.78 ; v1(20.1,19.725) 21.195,19.725 22.265,18.655 U9.6@23.25,18.655 ; v1(20.3,27.9) 21.7,29.3 22.425,29.3 22.627,29.502 v1(22.664,29.502) ; IC1.11@23.019,52.149 21.849,52.149 21.4,51.7 21.4,51.675 19.505,49.78 R19.1@19.48,49.78
  Bottom w0.3: JANALOG1.8@17.38,39.46 20.303,39.46 22.425,37.338 22.425,29.502 22.425,29.3 v1@22.664,29.3 ; v1(20.1,19.725) 20.3,19.925 v1(20.3,27.9) ; v1(22.664,29.502) v1@22.664,29.3 ; v1(27.3,29.625) 27.19,29.625 26.865,29.3 v1@22.664,29.3
SDR: Q5.1 U8.2 | length 6.3
  Top w0.2: v1(7.8,17.7) 8.35,17.7 8.5,17.55 U8.2@9.2,17.55 ; Q5.1@10.475,20.881 10.475,20.33 10.7,20.105 v1(10.7,20)
  Bottom w0.2: v1(7.8,17.7) 7.853,17.753 8.453,17.753 v1(10.7,20)
SDR2: Q1.1 U2.2 | length 5.9
  Top w0.2: v1(34.8,17.1) 34.937,17.1 35.287,16.75 U2.2@35.95,16.75
  Top w0.305: Q1.1@37.82,20.07 37.843,20.047 v1@37.843,19.666
  Bottom w0.2: v1(34.8,17.1) 37.1,19.4 v1(38,19.4)
SERVO1: IC1.14 U1.4 | length 4.5
  Top w0.3: IC1.14@24.424,50.744 24.424,48 24.492,47.932 U1.4@24.492,46.245
SERVO2: IC1.16 U1.2 | length 4.7
  Top w0.3: IC1.16@25.424,50.744 25.424,49.152 25.548,49.028 25.548,47.407 25.792,47.163 U1.2@25.792,46.245
SERVO3: IC1.13 U1.5 | length 4.5
  Top w0.3: U1.5@23.842,46.245 23.877,46.281 23.877,48.552 23.924,48.598 IC1.13@23.924,50.744
SERVO4: IC1.15 U1.3 | length 4.6
  Top w0.3: IC1.15@24.924,50.744 24.924,48.976 25.005,48.895 25.005,47.313 25.142,47.177 U1.3@25.142,46.245
SRV1: R39.1 SERVO1.1 U1.11 | length 28.3
  Top w0.3: v1(10.525,41.9) R39.1@11.575,41.9 ; U1.11@24.492,40.545 24.542,40.495 24.542,39.825 24.555,39.811
  Top w0.305: 24.555,39.811 24.722,39.644 24.722,38.978 24.8,38.9 v1(24.8,38.8)
  Bottom w0.3: SERVO1.1@3.53,42.54 8.89,42.54 9.7,43.35 10.525,43.35 ; v1(10.525,41.9) 10.525,43.35 ; v1(24.8,38.8) 24.76,38.84 24.76,39.603 21.013,43.35 10.525,43.35
SRV2: R42.1 SERVO2.1 U1.13 | length 25.2
  Top w0.3: R42.1@36.475,40.975 R42.1@36.49,40.975 ; SERVO2.1@46.308,37.288 SERVO2.1@46.48,37.46
  Top w0.305: U1.13@25.792,40.545 25.839,40.498 25.839,39.761 25.855,39.745 26.123,39.477 30.602,39.477 31.825,40.7 33.4,40.7 34.34,39.76 34.638,39.462 v1(36.419,39.462) 36.447,39.49 36.447,40.947 R42.1@36.475,40.975
  Bottom w0.305: v1(36.419,39.462) 36.455,39.462 36.468,39.45 44.451,39.45 46.44,37.46 SERVO2.1@46.48,37.46
SRV3: R46.1 SERVO3.1 U1.10 | length 28.5
  Top w0.3: v1(12.575,42.375) v1@12.575,42.54 ; v1(20.5,38.3) 22.3,38.3 23.805,39.805 23.805,40.508 U1.10@23.842,40.545
  PWR w0.3: v1@20.3,38.3 v1(20.5,38.3)
  Bottom w0.3: SERVO3.1@3.54,32.54 3.54,32.64 9.2,38.3 12.575,38.3 ; v1(12.575,42.375) 12.575,38.3 ; v1(20.5,38.3) 12.575,38.3
SRV4: R49.1 SERVO4.1 U1.12 | length 37.9
  Top w0.305: U1.12@25.142,40.545 25.189,40.498 25.189,39.611 27.2,37.6 29.921,37.6 29.932,37.611 31.024,37.611 31.612,38.2 34.495,38.2 36.895,35.8 37.6,35.8 ; R49.1@37.615,40.975 R49.1@37.6,40.975 37.6,35.8 ; SERVO4.1@46.237,27.227 SERVO4.1@46.47,27.46 ; SERVO4.1@46.47,27.97 47.65,29.15 47.65,33.4 46.8,34.25 43.255,34.25 41.705,35.8 37.6,35.8
STAT: DL12.C U9.4 | length 30.2
  Top w0.3: DL12.C@6.684,0.935 6.701,0.918 7.782,0.918 v1(7.8,0.9) ; v1(22.387,20.478) 22.49,20.478 22.951,20.018 23.479,20.018 24.25,19.247 U9.4@24.25,18.655
  Bottom w0.3: v1(7.8,0.9) 7.8,4.35 18.753,15.303 18.753,17.477 20.276,19 21.025,19 22.021,19.996 22.021,20.002 22.387,20.368 v1(22.387,20.478)
SW: C28.1 L1.2 Q5.2 U8.7 U8.8 U8.19 U8.20 U8.21 | length 1.3
  Top w0.2: C28.1@7.3,20.965 7.342,20.923 8.482,20.923 Q5.2@8.525,20.881
SW2: C46.1 L3.2 Q1.2 U2.7 U2.8 U2.19 U2.20 U2.21 | length 1.2
  Top w0.305: C46.1@34.815,20.335 34.95,20.2 35.669,20.2 35.701,20.168 35.847,20.168 35.87,20.145 Q1.2@35.87,20.07
SW_bq: C47.2 L2.1 U9.19 U9.20 | length 4.7
  Top w0.3: U9.19@26.655,15.25 27.535,15.25 ; U9.20@26.655,15.75 27.234,15.75 27.41,15.574 27.41,15.375 27.535,15.25 ; C47.2@27.839,15.25 27.535,15.25
  Top w0.5: C47.2@28,15.065 28,14 28.55,13.45 L2.1@29,13.45
SWCLK/MISO: CN1.4 IC1.19 R25.2 TP4.X | length 37.7
  Top w0.2: CN1.4@23.725,24.425 23.725,24.618 23.208,25.135 23.208,25.617 R25.2@23.1,25.725 27.175,25.725 v1(28.975,27.525)
  Top w0.305: IC1.19@27.329,51.649 27.599,51.649 28.137,51.111 28.548,51.111 v1(28.625,51.034)
  PWR w0.2: v1(28.625,51.034) 28.625,47.984 29.431,47.178 29.431,43.923 28.969,43.461 28.969,28.819 28.975,28.813 v1(28.975,27.525)
  Bottom w0.2: CN1.4@23.725,24.235 23.725,26.4 24.175,26.85 TP4.X@25,27.675
SWDIO/SS: CN1.2 IC1.20 TP5.X | length 34.6
  Top w0.305: IC1.20@27.329,52.149 27.331,52.151 27.942,52.151 28.291,52.5 v1(28.4,52.5)
  PWR w0.2: v1(22.376,26.551) 22.376,28.362 24.09,30.075 25.725,30.075 26.15,30.5 26.15,46.676 25.598,47.227 25.598,49.698 v1(28.4,52.5)
  Bottom w0.2: 22.416,25.172 22.416,26.512 v1(22.376,26.551) 22.418,26.593 22.418,27.633 TP5.X@22.46,27.675 ; CN1.2@22.455,24.235 22.458,24.238 22.458,25.172 22.46,25.175
TS_bq: R16.1 R45.2 U9.11 U9.12 | length 3.8
  Top w0.3: R16.1@21.15,13.8 R45.2@21.15,14.8 21.15,14.815 21.275,14.94 21.66,14.94 21.71,14.99 21.71,15.25 ; U9.12@22.07,15.25 U9.12@22.345,15.25 21.71,15.25 ; U9.11@22.345,15.75 21.886,15.75 21.71,15.574 21.71,15.25
TX1: B1.16 JDIGITAL1.1
USB_N: P2.1 U9.3 | length 54.1
  Top w0.2: v1(23.221,20.671) 23.318,20.574 23.603,20.574 23.889,20.288 23.889,20.174 24.331,19.732 24.445,19.732 24.773,19.404 24.773,18.678 U9.3@24.75,18.655
  PWR w0.2: v1(23.221,20.671) 23.124,20.768 23.124,21.053 22.605,21.571 20.894,21.571 18.746,23.72 18.746,45.588 19.531,46.373 19.531,54.173 26.146,60.788 28.549,60.788 29.418,59.919 29.418,59.565 29.535,59.448 30.285,59.448 P2.1@30.461,59.272
USB_P: P1.1 U9.2 | length 52.8
  Top w0.2: v1(24.551,20.401) 24.551,20.387 24.492,20.327 25.227,19.592 25.227,18.678 U9.2@25.25,18.655
  PWR w0.2: v1(24.551,20.401) 24.702,20.401 23.078,22.025 21.083,22.025 19.2,23.908 19.2,45.4 19.985,46.185 19.985,53.985 26.334,60.334 28.361,60.334 28.964,59.731 28.964,59.565 28.847,59.448 28.097,59.448 P1.1@27.921,59.272
V_READ: C63.1 C64.2 IC1.1 R15.1 R38.2 | length 98
  Top w0.35: R38.2@19.2,1.912 R15.1@19.2,2.528 ; R15.1@19.2,2.6 20.325,2.6 C63.1@20.4,2.525 ; C63.1@20.597,2.403 21.153,2.403 v1(22.169,1.388) ; IC1.1@26.424,55.054 26.424,55.052 26.449,55.027 v1@27.3,55.027 ; v1(27.3,55) v1@27.3,55.027 ; C64.2@28.565,55 28.538,55.027 v1@27.3,55.027 ; v1(29.8,53) 31.8,51 34.45,51 40.327,45.123 46.977,45.123 48.3,43.8 v1(48.3,8)
  PWR w0.35: v1(22.169,1.388) 22.252,1.305 34.255,1.305 36.251,3.3 44.259,3.3 46.659,5.7 47.995,5.7 48.3,6.005 v1(48.3,8) ; v1(27.3,55) 29.2,55 29.7,54.5 29.7,53.4
VBATT: C4.2 C6.2 C11.2 C18.2 L1.1 L3.1 Q3.5 R17.2 R18.2 U2.6 U2.11 U8.6 U8.11 U9.13 U9.14 | length 17.1
  Top w0.2: U2.11@38.85,14.75 38.875,14.725 39.308,14.725 39.425,14.608 39.425,14.085 39.451,14.059 v1(39.397,14.059)
  Top w0.305: U8.11@12.1,15.55 12.27,15.55 12.298,15.523 12.298,15.352 12.3,15.35 v1(12.3,14.7) ; 23.25,13.45 U9.13@23.25,14.345 ; 23.75,13.45 U9.14@23.75,14.345 ; R17.2@32.525,15.64 32.525,15.275 33.6,14.2 34.4,14.2
  Bottom w0.2: v1(39.397,14.059) 39.397,9.203 v1(39.4,9.2)
  Bottom w0.305: v1(7.6,12.7) 9.6,14.7 v1(12.3,14.7)
VBUS: B1.12 CBUS.1 JANALOG1.12 U9.1 U9.24 VBUS.X | length 2.1
  Top w0.35: U9.1@25.75,18.655 U9.1@25.775,18.68
  Bottom w0.2: JANALOG1.12@17.38,29.3 17.58,29.1 19.194,29.1 VBUS.X@19.347,28.947
VCP_M1: C8.1 U4.18 | length 1.2
  Top w0.2: U4.18@20.625,71.6 20.675,71.55 20.675,70.464 C8.1@20.739,70.4
pads on no net: B1.+3V3 B1.GND B1.N B1.P B1.RESETN B1.SWCLK B1.SWDIO CN1.6 CN1.7 CN1.8 fid1.1 fid2.1 fid3.1 IC1.21 IC1.22 Q1.M1 Q1.M2 Q3.M1 Q3.M2 Q5.M1 Q5.M2 U1.6 U1.9 U3.1 U3.7 U3.8 U3.12 U3.13 U3.21 U3.22 U3.23 U3.24 U4.5 U4.19 U4.20 U4.21 U4.22 U5.5 U5.19 U5.20 U5.21 U5.22 U6.5 U6.20 U6.21 U6.22 U7.5 U7.20 U7.21 U7.22 U$1.3

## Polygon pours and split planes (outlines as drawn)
GND on Top "GND_L01_P201" (solid, pour order 201): 47.437,0.067 2.583,0.067 cw(c2.583,2.65) 0,2.65 0,77.343 cw(c2.725,77.343) 2.725,80.068 47.122,80.068 cw(c47.122,77.19) 50,77.189 50,2.631 cw(c47.437,2.63)
+VM on Top "+VM_L01_P196" (solid, pour order 196): 34.575,20.9 40.8,20.9 40.8,34.7 34.575,34.7
M4- on Top "M4-_L01_P188" (solid, pour order 188): 33.8,63.5 35.7,61.6 44,61.6 45.524,63.124 47.076,63.124 47.437,62.763 47.437,61.337 45.325,59.225 35.175,59.225 32.4,62 32.4,63 33,63 33,63.5
M4+ on Top "M4+_L01_P186" (solid, pour order 186): 35.065,66.4 35.945,65.52 40.72,65.52 41.97,64.27 47.995,64.27 48.5,64.775 48.5,66.225 47.925,66.8 42.4,66.8 41.3,67.9 32.5,67.9 32.5,67 33,67 33,66.4
M2- on Top "M2-_L01_P180" (solid, pour order 180): 32.5,70.8 32.675,70.625 33.05,70.625 33.575,70.1 36.625,70.1 38.775,67.95 47.825,67.95 48.2,68.325 48.2,69.95 47.45,70.7 39.65,70.7 38.175,72.175 34.225,72.175 33.8,72.6 33,72.6 33,72 32.5,72
M2+ on Top "M2+_L01_P178" (solid, pour order 178): 42.323,74.977 43.748,74.977 44.675,74.1 44.8,74.1 47.7,74.1 48.2,73.6 48.2,71.9 47.875,71.575 42.225,71.575 38.3,75.5 33,75.5 33,76 32.5,76 32.5,77.525 39.775,77.525
M3- on Top "Top-M3- 1" (solid, pour order 172): 5.6,61.9 4.5,63 4.3,63.2 3,63.2 2.407,62.607 2.407,61.493 4.65,59.25 14.75,59.25 17.6,62.1 17.6,63.4 17.3,63.7 16.175,63.7 14.375,61.9
M3+ on Top "Top-M3-" (solid, pour order 170): 17.6,65.85 17.6,68.1 7.9,68.1 6.6,66.8 2.85,66.8 2.225,66.175 2.225,64.65 2.785,64.09 7.59,64.09 9.35,65.85
M1- on Top "Top-M1-" (solid, pour order 168): 15.42,72.52 14.795,71.895 12.081,71.906 10.65,70.475 2.875,70.475 2.15,69.75 2.15,68.55 2.6,68.1 11.9,68.1 14,70.2 17.7,70.2 17.7,72 17,72 17,72.52
M1+ on Top "Top-M1+" (solid, pour order 166): 17.7,76 17,76 17,75.3 11.45,75.3 7.775,71.625 2.78,71.625 2.475,71.93 2.475,73.35 4.1,74.975 7.35,74.975 10.2,77.825 17.7,77.825
+VM2 on Top "+VM2_L01_P149" (solid, pour order 149): 9.3,24 9.3,24.2 9.3,35.625 16,35.625 16,30 16,27.6 13.6,27.6 13.6,20.8 11.2,20.8 11.2,21.7 8.3,21.7 8.3,24
GND on Top "Top-GND 2" (solid, pour order 199): 37.525,18.675 37.525,13.5 38.425,13.5 38.5,13.575 38.5,18.65
+VM2 on Top "+VM2_L01_P194" (solid, pour order 194): 17,65.5 17,63.9 16.3,63.9 14.4,62 11.5,62 11.5,65.1 11.9,65.5
+VM on Top "poligonTest" (solid, pour order 190): 33,66.1 33,64.5 33.8,64.5 34.5,63.8 34.5,61.9 38.4,61.9 38.4,66.4 33.3,66.4
+VM on Top "+VM_L01_P184" (solid, pour order 184): 38.4,75.125 38.4,71.989 34.9,71.989 34.9,72.7 34.355,73.245 33,73.245 33,75.1 33.9,75.1 34.3,75.5 38.025,75.5
+VM2 on Top "+VM2_L01_P182" (solid, pour order 182): 17,74.5 14.6,74.5 14.6,75.203 14.451,75.351 14.4,75.3 11.4,75.3 11.4,70.5 13.2,70.5 15.4,72.7 17,72.7
+5V on Top "+5V_L01_P176" (solid, pour order 176): 27.5,18.8 27.5,20.2 31.4,20.2 31.4,16.4 29.2,16.4 28.501,17.099 26.3,17.099 26.3,17.4 27.4,17.4 27.5,17.5
VBUS on Top "VBUS_L01_P174" (solid, remove dead copper, pour order 174): 16.424,28.976 16.424,28.388 16.855,27.957 18.066,27.957 18.29,27.733 18.3,27.05 18.3,22.625 19.9,21.025 24.995,21.025 24.995,18.2 26.2,18.2 26.2,17.6 27.2,17.6 27.2,19.4 26.7,19.4 26.7,21.675 26.175,22.2 21.7,22.2 19.975,23.925 19.975,28.4 18.175,30.2 16.522,30.2 16.424,30.102
VBATT on Top "VBATT_L01_P153" (solid, pour order 153): 36.297,14.912 36.297,12.022 36.253,11.978 38.85,11.978 40.7,11.978 40.7,4.7 23.466,4.7 19.291,8.875 15.8,8.875 15.8,6 7.5,6 7,6.5 7,14.912 7.8,15.712 8.188,15.712 9.7,15.712 9.573,12.022 20.422,12.022 21.53,13.13 21.53,13.8 26,13.8 29.6,10.2 34,10.2 34,14.912
SW2 on Top "sw2" (solid, pour order 152): 39.58,11.02 37.325,13.275 37.325,20.3 37.2,20.3 35.3,20.3 35.3,18.4 36.2,17.5 36.2,16.9 36.2,11.205 36.563,10.861
BATT+1 on Top "BATT-DIRECT" (solid, pour order 150): 22.32,9.08 22.2,8.96 22.2,5.8 25.4,5.8 25.5,5.9 25.5,0.2 12.9,0.2 12.8,0.3 12.8,5.8 15.8,5.8 15.8,9.6 21.8,9.6
GND on Top "GND_L01_P147" (solid, pour order 147): 10.7,19.8 10.7,13.7 11.7,12.7 11.9,12.9 19.2,12.9 19.1,13 19.1,14.2 11.8,14.2 11.5,14.5 11.8,14.8 11.8,19.5 15.9,19.5 15.9,27.6 13.6,27.6 13.6,20.8 11.7,20.8
GND on Top "GND_L01_P148" (solid, pour order 148): 11.7,17.853 12.013,17.54 14.293,17.54 14.293,14.3 17.6,14.3 17.6,18.3 16.4,19.5 11.7,19.5
SW on Top "SW_L01_P146" (solid, pour order 146): 9.8,14.55 9,13.75 9,12.1 12.2,12.1 10.8,13.5 10.55,13.5 10.55,19.95 10.1,20.4 10.1,21.3 8.2,21.3 8.1,21.2 8.1,19.175 9.8,17.475
GND on Bottom "Polygon_2_Net_GND" (solid, remove dead copper, pour order 164): 0.201,81.996 0,0 48.362,0.125 ccw(c48.359,2.332) 50.566,2.333 50.517,82.127
+VM on Bottom "Polygon_3_Net_+VM" (solid, remove dead copper, pour order 163): 13.252,58.252 10.047,58.252 10.047,55.548 13.252,55.548
no net on Bottom "Polygon_2_Net_M3-" (solid, remove dead copper, pour order 162): 12.933,72.352 13.63,72.932 16.837,72.932 16.837,70.928 13.322,70.928 12.933,71.317
+3.3V on GND "+3.3V_L03_P160" (solid, pour order 160): 47.437,0 2.583,0 cw(c2.583,2.583) 0,2.583 0,77.275 cw(c2.725,77.275) 2.725,80 47.122,80 cw(c47.122,77.122) 50,77.122 50,2.563 cw(c47.437,2.563)
+VM2 on GND "PWR-+VM2" (solid, pour order 159): 18.402,56.025 16.05,56.025 16.05,53.525 16.225,53.35 18.525,53.35 18.525,20.525 16.25,20.525 16.25,23.2 7.4,23.2 7.4,72.7 10.85,76.15 18.402,76.15
+VM on GND "PWR-+VM" (solid, pour order 158): 40.3,76.1 43.2,73.2 43.2,23.1 36.1,23.1 33.2,26 33.2,76.1
+5V on GND "PWR-+5V" (solid, pour order 157): 5,12.625 5.225,12.4 45.3,12.4 45.3,20.7 45.2,20.8 43.225,18.825 5,18.825
+5V on GND "Polygon_1_Net_+5V" (solid, remove dead copper, pour order 156): 5.302,41.7 1.722,41.7 1.722,14.6 5.316,14.6
+5V on GND "Polygon_2_Net_+5V" (solid, remove dead copper, pour order 155): 48.187,16.1 48.187,18.8 48.187,41.675 44.965,41.675 44.965,8.8 48.187,8.8
GND on PWR "GND_L02_P121" (solid, pour order 154): 47.437,0 2.583,0 cw(c2.583,2.583) 0,2.583 0,77.275 cw(c2.725,77.275) 2.725,80 47.122,80 cw(c47.122,77.122) 50,77.122 50,2.563 cw(c47.437,2.563)

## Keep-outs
Top:
  region: 25.276,33.5 24.275,33.5 24.275,30.5 25.75,30.5 25.75,33.512
PWR:
  region: 25.276,33.5 24.275,33.5 24.275,30.5 25.75,30.5 25.75,33.512
GND:
  region: 25.326,33.494 24.325,33.494 24.325,30.494 25.8,30.494 25.8,33.506
Bottom:
  region: 25.276,33.5 24.275,33.5 24.275,30.5 25.75,30.5 25.75,33.512
Keep-Out Layer:
  the board outline again, w0

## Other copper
Top:
  pour cut-out: 39.075,17.39 39.075,18.225 39.775,18.925 44.45,18.925 44.75,18.625 44.75,13.175 44.675,13.1 41.5,13.1 41.5,12.775 44.8,12.775 45.125,13.1 45.125,18.75 44.75,19.125 39.675,19.125 38.875,18.325 38.875,17.39
  pour cut-out: 12.858,14.3 13.191,14.3 13.6,14.3 13.7,14.3 17.5,14.3 17.75,14.55 17.75,18.124 16.261,19.267 12.892,19.267 12.2,18.575 12.2,18.3 11.9,18.3 11.9,18.625 12.825,19.55 16.495,19.55 18.1,18.293 18.1,14.375 17.725,14 12.871,14

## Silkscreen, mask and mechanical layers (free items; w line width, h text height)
Top Overlay:
Route Tool Path:
  lines w2: -1,77.575 -1,38 -1,2.583 ccw(c2.583,2.583) 2.583,-1 24.358,-1 ; 6.725,81 43.122,81 ; 27.358,-1 47.358,-1 ; 50.994,37.5 51.05,76.875 ; 51,38 51,2.563 ; -1,77.275 cw(c2.725,77.275) 2.725,81 ; -1,77.275 ccw(c2.725,77.275) -1,77.275 ; -1,77.275 -1,77.275 ; 2.725,81 ccw(c2.725,80) 2.725,81 ; 2.725,81 ccw(c2.725,80) 2.725,81 ; 47.122,81 ccw(c47.122,80) 47.122,81 ; 47.122,81 ccw(c47.122,80) 47.122,81 ; 47.122,81 cw(c47.122,77.122) 51,77.122 ; 47.437,-1 ccw(c47.437,0) 47.437,-1 ; 47.437,-1 ccw(c47.437,0) 47.437,-1 ; 47.437,-1 ccw(c47.437,2.563) 51,2.563 ; 51,2.563 ccw(c47.437,2.563) 51,2.563 ; 51,2.563 51,2.563 ; 51,77.122 ccw(c47.122,77.122) 51,77.122
Board:
  the board outline again, w0.127
Top Assembly:
Unrouted:
  drawing of 194 lines, arcs and shapes, not listed
Notes:
  text "M2+" at 44.663,72.016 h1.5
  text "M1+" at 8.105,71.919 h1.5
  text "M1-" at 7.806,68.625 h1.5
  text "M2-" at 44.663,68.291 h1.5
  text "M3+" at 8.105,65.452 h1.5
  text "M4+" at 44.663,64.923 h1.5
  text "M3-" at 7.806,61.857 h1.5
  text "M4-" at 44.663,61.515 h1.5
  text "+3.3V" at 9.094,58.29 h1.5
  text "+3.3V" at 44.663,57.87 h1.5
  text "HA1" at 7.889,55.076 h1.5
  text "HA2" at 44.663,54.312 h1.5
  text "HB1" at 7.889,51.349 h1.5
  text "HB2" at 44.604,50.876 h1.5
  text "GND" at 44.663,47.781 h1.5
  text "GND" at 8.473,47.628 h1.5
  text "SERVO1" at 10.768,42.796 h1.5
  text "GND" at 44.663,42.492 h1.5
  text "+5V" at 7.975,40.111 h1.5
  text "+5V" at 44.663,39.776 h1.5
  text "GND" at 8.473,37.571 h1.5
  text "SERVO2" at 44.707,37.345 h1.5
  text "SERVO3" at 10.954,32.945 h1.5
  text "GND" at 44.663,32.627 h1.5
  text "+5V" at 7.975,30.509 h1.5
  text "+5V" at 44.663,29.862 h1.5
  text "GND" at 8.473,27.86 h1.5
  text "SERVO4" at 44.539,27.433 h1.5
  text "+3.3V" at 9.1,22.6 h1.5
  text "GND" at 44.663,22.575 h1.5
  text "A7" at 7.216,20.335 h1.5
  text "A2" at 44.463,20.119 h1.5
  text "GND" at 8.473,17.741 h1.5
  text "+3.3V" at 44.663,17.348 h1.5
  text "+3.3V" at 9.2,12.2 h1.5
  text "GND" at 44.663,12.183 h1.5
  text "A6" at 7.223,9.84 h1.5
  text "A3" at 44.609,9.397 h1.5
  text "GND" at 8.473,7.3 h1.5
  text "+3.3V" at 44.663,6.802 h1.5
  text "GND" at 10.959,4.561 h1.5
  text "BATT" at 16.771,4.475 h1.5
  text "GND" at 28.775,0.775 h1.5
  text "V0.1" at 37.9,0.75 h2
